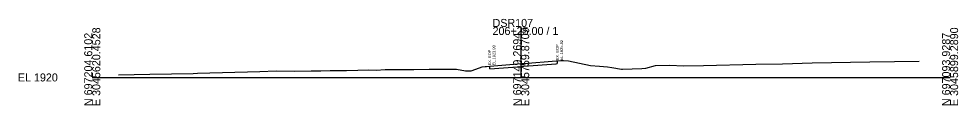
# Model space of a CAD drawing. Extents: x -26 to 19003, y -31 to 24541.
# Drawn here: x 1974.3 to 2302.8, y 9990.3 to 10020.5 of the extents above; entities that cross this region are included whole.
import ezdxf

# ---------------------------------------------------------------- set-up
doc = ezdxf.new("R2010")
doc.units = 0
for name, color, linetype in [('DESIGN - SHEET - Light Grid', 7, 'Continuous'), ('SURVEY - GROUND - Existing Pavement Layer', 7, 'Continuous'), ('SURVEY - GROUND - Existing Pavement Text', 7, 'Continuous'), ('SURVEY - GROUND - Top of Ground', 7, 'Continuous')]:
    doc.layers.add(name, color=color, linetype=linetype)

msp = doc.modelspace()

# ---------------------------------------------------------------- linework, layer by layer
at = {"layer": 'DESIGN - SHEET - Light Grid'}
for p, q in [((2150, 10000), (2150, 10017.64)), ((2000, 10000), (2150, 10000)), ((2150, 10000), (2300, 10000))]:
    msp.add_line(p, q, dxfattribs=at)
at = {"layer": 'SURVEY - GROUND - Existing Pavement Layer'}
for p, q in [((2138.99, 10002.99), (2138.99, 10003.99)), ((2138.99, 10002.99), (2150.22, 10003.87)), ((2150.22, 10003.87), (2150.88, 10003.93)), ((2150.88, 10003.93), (2162.27, 10004.81)), ((2162.27, 10004.81), (2162.64, 10004.82)), ((2162.64, 10005.82), (2162.64, 10004.82))]:
    msp.add_line(p, q, dxfattribs=at)
at = {"layer": 'SURVEY - GROUND - Top of Ground'}
msp.add_lwpolyline([(2009.18, 10000.86), (2020.12, 10001.09), (2035.24, 10001.39), (2036.84, 10001.46), (2058.62, 10002.05), (2064.28, 10002.27), (2070.73, 10002.23), (2076.56, 10002.29), (2079.91, 10002.36), (2083.2, 10002.37), (2088.91, 10002.43), (2092.89, 10002.52), (2096.78, 10002.63), (2099.28, 10002.56), (2102.48, 10002.76), (2112.48, 10002.81), (2117.85, 10002.84), (2126.25, 10002.88), (2127.41, 10002.88), (2130.52, 10002.29), (2132.46, 10002.32), (2132.87, 10002.45), (2136.41, 10003.69), (2137.45, 10003.82), (2137.83, 10003.86), (2138.99, 10003.99), (2150.22, 10004.87), (2150.88, 10004.93), (2162.27, 10005.81), (2162.64, 10005.82), (2163.82, 10005.88), (2164.76, 10005.87), (2166.5, 10005.86), (2174.19, 10004.21), (2177.4, 10003.91), (2180.16, 10003.65), (2181.65, 10003.42), (2185.14, 10002.91), (2185.46, 10002.89), (2192.22, 10003.14), (2193.56, 10003.27), (2196.98, 10004.23), (2201.93, 10004.27), (2206.89, 10004.08), (2213.76, 10004.22), (2232.09, 10004.69), (2241.39, 10004.76), (2251.74, 10005.1), (2271.88, 10005.5), (2289.22, 10005.68)], dxfattribs=at)

# ---------------------------------------------------------------- texts
at = {"layer": 'DESIGN - SHEET - Light Grid'}
for s, p in [('DSR107', (2140, 10017.64)), ('206+25.00 / 1', (2140, 10014.84)), ('EL 1920', (1974, 9998.6))]:
    msp.add_text(s, height=2.8, dxfattribs=at).set_placement(p)
for s, p in [('E 3045620.4528', (2002.8, 9990)), ('E 3045759.8709', (2152.8, 9990)), ('E 3045899.2890', (2302.8, 9990)), ('N 697204.6102', (2000, 9990)), ('N 697149.2694', (2150, 9990)), ('N 697093.9287', (2300, 9990))]:
    msp.add_text(s, height=2.8, rotation=90, dxfattribs=at).set_placement(p)
at = {"layer": 'SURVEY - GROUND - Existing Pavement Text'}
for s, p in [('EL.1923.99', (2140.99, 10004.19)), ('EX. EOP', (2163.14, 10006.02)), ('EL.1925.82', (2164.64, 10006.02)), ('EX. EOP', (2139.49, 10004.19))]:
    msp.add_text(s, height=1, rotation=90, dxfattribs=at).set_placement(p)

doc.saveas('drawing.dxf')
